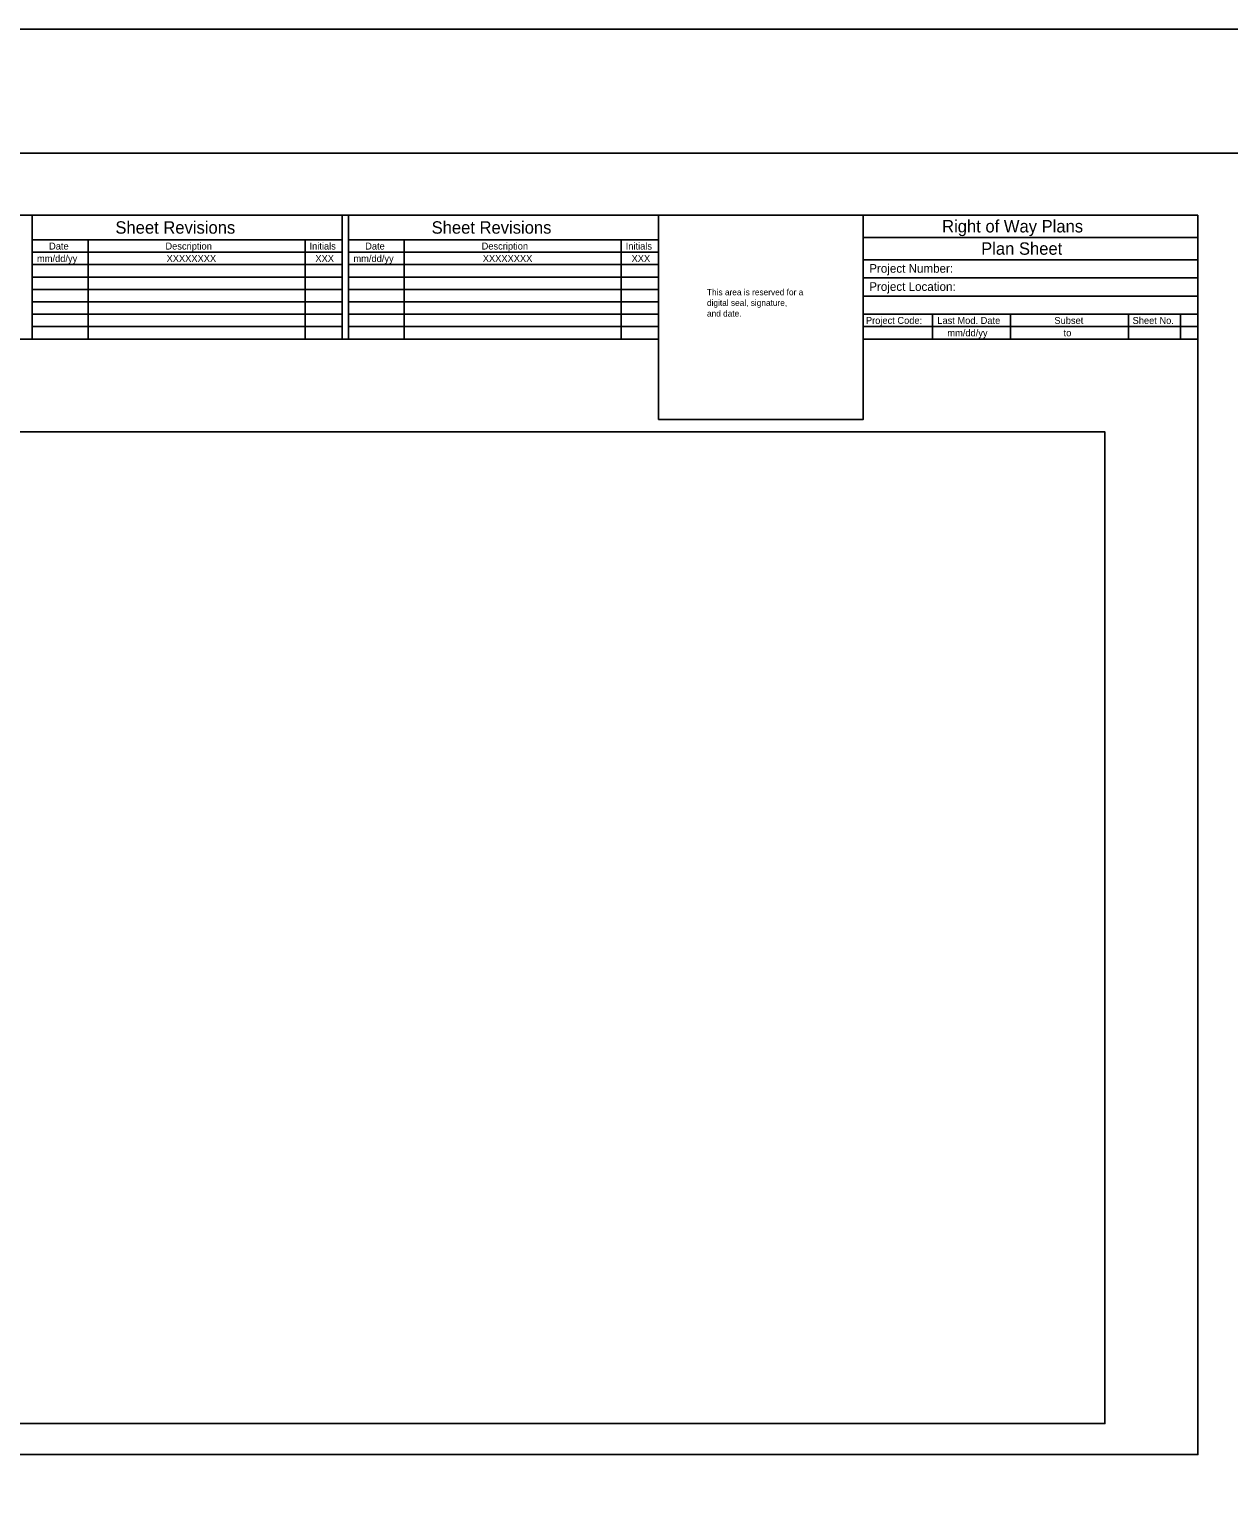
# Model space of a CAD drawing. Extents: x 0 to 3, y 0 to 2.
# Drawn here: x 0.715 to 1.521, y 1.02 to 2 of the extents above; entities that cross this region are included whole.
import ezdxf

# ---------------------------------------------------------------- set-up
doc = ezdxf.new("R2010")
doc.units = 0
for name, color, linetype in [('DRAFT_Information-No Plot', 7, 'Continuous'), ('SHEET_Lines', 7, 'Continuous'), ('SHEET_North Arrow', 7, 'Continuous'), ('SHEET_Plot Boundary', 7, 'Continuous'), ('SHEET_Text-Border Info', 7, 'Continuous')]:
    doc.layers.add(name, color=color, linetype=linetype)

msp = doc.modelspace()

# ---------------------------------------------------------------- linework, layer by layer
at = {"layer": 'DRAFT_Information-No Plot'}
msp.add_lwpolyline([(0.27083, 1.72917), (1.4375, 1.72917), (1.4375, 1.0625), (0.27083, 1.0625)], close=True, dxfattribs=at)
at = {"layer": 'SHEET_Lines'}
for p, q in [((0.20833, 1.875), (1.5, 1.875)), ((0.71667, 1.875), (0.71667, 1.79167)), ((0.925, 1.875), (0.925, 1.79167)), ((0.92917, 1.875), (0.92917, 1.79167)), ((1.1375, 1.875), (1.1375, 1.79167)), ((1.275, 1.875), (1.275, 1.79167)), ((1.5, 1.875), (1.5, 1.79167)), ((0.71667, 1.85833), (0.925, 1.85833)), ((0.75417, 1.79167), (0.75417, 1.85833)), ((0.9, 1.79167), (0.9, 1.85833)), ((0.92917, 1.85833), (1.1375, 1.85833)), ((0.96667, 1.79167), (0.96667, 1.85833)), ((1.1125, 1.79167), (1.1125, 1.85833)), ((1.5, 1.86), (1.275, 1.86)), ((0.71667, 1.85), (0.925, 1.85)), ((0.92917, 1.85), (1.1375, 1.85)), ((1.5, 1.845), (1.275, 1.845)), ((0.71667, 1.84167), (0.925, 1.84167)), ((0.71667, 1.83333), (0.925, 1.83333)), ((0.92917, 1.84167), (1.1375, 1.84167)), ((0.92917, 1.83333), (1.1375, 1.83333)), ((1.5, 1.83278), (1.275, 1.83278)), ((0.71667, 1.825), (0.925, 1.825)), ((0.92917, 1.825), (1.1375, 1.825)), ((0.71667, 1.81667), (0.925, 1.81667)), ((0.92917, 1.81667), (1.1375, 1.81667)), ((1.5, 1.82056), (1.275, 1.82056)), ((0.71667, 1.80833), (0.925, 1.80833)), ((0.92917, 1.80833), (1.1375, 1.80833)), ((1.5, 1.80833), (1.275, 1.80833)), ((1.32167, 1.79167), (1.32167, 1.80833)), ((1.37417, 1.79167), (1.37417, 1.80833)), ((1.45333, 1.79167), (1.45333, 1.80833)), ((1.48833, 1.79167), (1.48833, 1.80833)), ((0.71667, 1.8), (0.925, 1.8)), ((0.92917, 1.8), (1.1375, 1.8)), ((1.5, 1.8), (1.275, 1.8))]:
    msp.add_line(p, q, dxfattribs=at)
for points in [[(2.95833, 0.08333), (0.125, 0.08333), (0.125, 1.91667), (2.95833, 1.91667)], [(1.1375, 1.7375), (1.275, 1.7375), (1.275, 1.875), (1.1375, 1.875)]]:
    msp.add_lwpolyline(points, close=True, dxfattribs=at)
msp.add_lwpolyline([(1.1375, 1.79167), (0.20833, 1.79167), (0.20833, 1.04167), (1.5, 1.04167), (1.5, 1.79167), (1.275, 1.79167)], dxfattribs=at)
at = {"layer": 'SHEET_Plot Boundary'}
msp.add_lwpolyline([(0, 2), (3, 2), (3, 0), (0, 0)], close=True, dxfattribs=at)

# ---------------------------------------------------------------- texts
at = {"layer": 'DRAFT_Information-No Plot'}
for s, height, p in [('This area is reserved for a', 0.0041667, (1.1701, 1.82108)), ('digital seal, signature,', 0.0041667, (1.1701, 1.81394)), ('and date.', 0.004167, (1.1701, 1.80679))]:
    msp.add_text(s, height=height, dxfattribs=at).set_placement(p)
at = {"layer": 'SHEET_North Arrow'}
for s, height, p in [('Right of Way Plans', 0.0083333, (1.32813, 1.86333)), ('Sheet Revisions', 0.0083333, (0.77255, 1.8625)), ('Sheet Revisions', 0.0083333, (0.98505, 1.8625)), ('Plan Sheet', 0.008333, (1.35438, 1.84833))]:
    msp.add_text(s, height=height, dxfattribs=at).set_placement(p)
at = {"layer": 'SHEET_Text-Border Info'}
for s, height, p in [('Date', 0.004667, (0.72795, 1.85183)), ('Description', 0.0046667, (0.80616, 1.85183)), ('Initials', 0.004667, (0.90299, 1.85183)), ('Date', 0.004667, (0.9404, 1.85183)), ('Description', 0.0046667, (1.01866, 1.85183)), ('Initials', 0.004667, (1.11549, 1.85183)), ('mm/dd/yy', 0.004667, (0.71987, 1.8435)), ('XXXXXXXX', 0.004667, (0.80694, 1.8435)), ('XXX', 0.004667, (0.90694, 1.8435)), ('mm/dd/yy', 0.004667, (0.93251, 1.8435)), ('XXXXXXXX', 0.004667, (1.01944, 1.8435)), ('XXX', 0.004667, (1.11944, 1.8435)), ('Project Number:', 0.0058333, (1.27917, 1.83625)), ('Project Location:', 0.0058333, (1.27917, 1.82403)), ('Project Code:', 0.0046667, (1.27693, 1.80183)), ('Last Mod. Date', 0.0046667, (1.32491, 1.80183)), ('Subset', 0.004667, (1.40359, 1.80183)), ('Sheet No.', 0.004667, (1.45615, 1.80183)), ('mm/dd/yy', 0.004667, (1.33165, 1.7935)), (' to ', 0.004667, (1.40806, 1.7935))]:
    msp.add_text(s, height=height, dxfattribs=at).set_placement(p)

doc.saveas('drawing.dxf')
